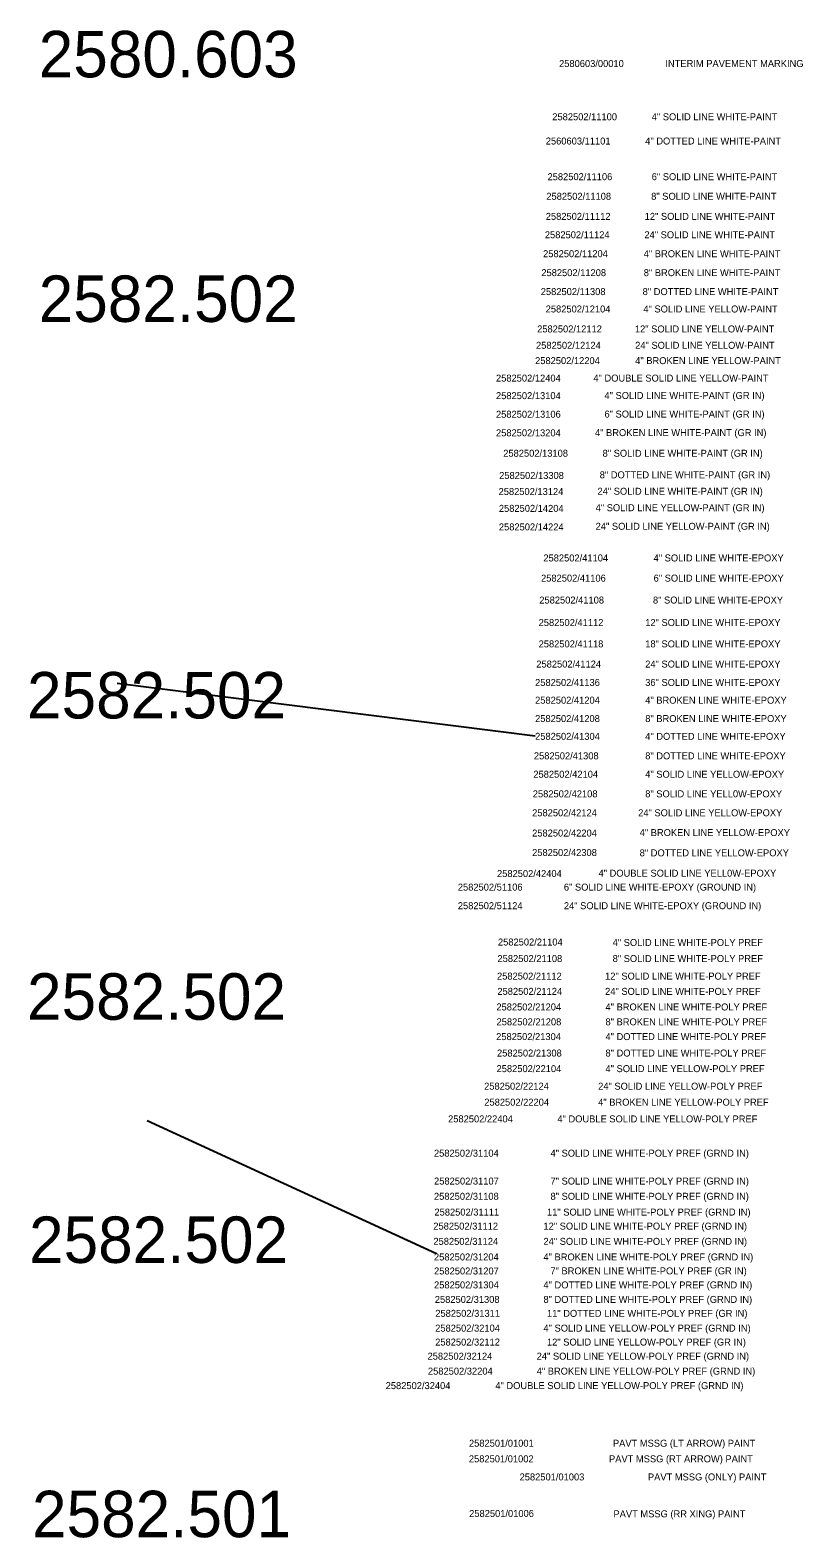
# Model space of a CAD drawing. Extents: x 2147712 to 2176316, y 2125036 to 2131746.
# Drawn here: x 2155869 to 2156701, y 2127854 to 2129477 of the extents above; entities that cross this region are included whole.
import ezdxf

# ---------------------------------------------------------------- set-up
doc = ezdxf.new("R2010")
doc.units = 0
doc.layers.add('DETAIL TXT', color=7, linetype='Continuous')
doc.layers.add('PVMT STRP', color=7, linetype='Continuous')

msp = doc.modelspace()

# ---------------------------------------------------------------- linework, layer by layer
at = {"layer": 'DETAIL TXT'}
for p, q in [((2156412.9, 2128716.8), (2155962.8, 2128773.5)), ((2156306.7, 2128159.6), (2155995.1, 2128302.9))]:
    msp.add_line(p, q, dxfattribs=at)

# ---------------------------------------------------------------- texts
for s, height, p in [('2580.603', 50, (2155878.4, 2129426.1)), ('2580603/00010', 7.5, (2156438.7, 2129437.2)), ('INTERIM PAVEMENT MARKING', 7.5, (2156553.2, 2129437.2)), ('2582502/11100', 7.5, (2156431.4, 2129379.9)), ('4" SOLID LINE WHITE-PAINT', 7.5, (2156538.5, 2129379.9)), ('2560603/11101', 7.5, (2156424.4, 2129353.8)), ('4" DOTTED LINE WHITE-PAINT', 7.5, (2156531.5, 2129353.8)), ('2582502/11106', 7.5, (2156426.3, 2129315.4)), ('6" SOLID LINE WHITE-PAINT', 7.5, (2156538.5, 2129315.4)), ('2582502/11108', 7.5, (2156425, 2129294.3)), ('8" SOLID LINE WHITE-PAINT', 7.5, (2156537.9, 2129294.3)), ('2582502/11112', 7.5, (2156424.4, 2129272.7)), ('12" SOLID LINE WHITE-PAINT', 7.5, (2156530.9, 2129272.7)), ('2582502/11124', 7.5, (2156423.4, 2129252.9)), ('24" SOLID LINE WHITE-PAINT', 7.5, (2156530.6, 2129252.9)), ('2582502/11204', 7.5, (2156421.5, 2129232.5)), ('4" BROKEN LINE WHITE-PAINT', 7.5, (2156529.9, 2129232.5)), ('2582.502', 50, (2155878.4, 2129162.8)), ('2582502/11208', 7.5, (2156419.6, 2129212.1)), ('8" BROKEN LINE WHITE-PAINT', 7.5, (2156529.9, 2129212.1)), ('2582502/11308', 7.5, (2156419, 2129191.7)), ('8" DOTTED LINE WHITE-PAINT', 7.5, (2156528.7, 2129191.7)), ('2582502/12104', 7.5, (2156424.3, 2129173)), ('4" SOLID LINE YELLOW-PAINT', 7.5, (2156529.5, 2129173)), ('2582502/12112', 7.5, (2156415.1, 2129151.5)), ('12" SOLID LINE YELLOW-PAINT', 7.5, (2156520.4, 2129151.5)), ('2582502/12124', 7.5, (2156413.9, 2129133.9)), ('24" SOLID LINE YELLOW-PAINT', 7.5, (2156520.7, 2129133.9)), ('2582502/12204', 7.5, (2156412.9, 2129117.4)), ('4" BROKEN LINE YELLOW-PAINT', 7.5, (2156520.7, 2129117.4)), ('2582502/12404', 7.5, (2156370.8, 2129098.6)), ('4" DOUBLE SOLID LINE YELLOW-PAINT', 7.5, (2156475.7, 2129098.6)), ('2582502/13104', 7.5, (2156370.8, 2129079.7)), ('4" SOLID LINE WHITE-PAINT (GR IN)', 7.5, (2156487.6, 2129079.9)), ('2582502/13106', 7.5, (2156370.8, 2129059.7)), ('6" SOLID LINE WHITE-PAINT (GR IN)', 7.5, (2156487.6, 2129059.9)), ('2582502/13204', 7.5, (2156370.8, 2129039.7)), ('4" BROKEN LINE WHITE-PAINT (GR IN)', 7.5, (2156477.4, 2129039.9)), ('2582502/13108', 7.5, (2156378.6, 2129017.7)), ('8" SOLID LINE WHITE-PAINT (GR IN)', 7.5, (2156485.6, 2129017.7)), ('2582502/13308', 7.5, (2156374.2, 2128993.8)), ('8" DOTTED LINE WHITE-PAINT (GR IN)', 7.5, (2156482.5, 2128994.5)), ('2582502/13124', 7.5, (2156373.6, 2128976.5)), ('24" SOLID LINE WHITE-PAINT (GR IN)', 7.5, (2156480.1, 2128976.8)), ('2582502/14204', 7.5, (2156373.9, 2128958.4)), ('4" SOLID LINE YELLOW-PAINT (GR IN)', 7.5, (2156478.1, 2128959.1)), ('2582502/14224', 7.5, (2156373.9, 2128938.4)), ('24" SOLID LINE YELLOW-PAINT (GR IN)', 7.5, (2156478.1, 2128939.1)), ('2582502/41104', 7.5, (2156421.8, 2128905)), ('4" SOLID LINE WHITE-EPOXY', 7.5, (2156540.5, 2128905)), ('2582502/41106', 7.5, (2156419.3, 2128883.3)), ('6" SOLID LINE WHITE-EPOXY', 7.5, (2156540.5, 2128883.3)), ('2582502/41108', 7.5, (2156417.4, 2128859.7)), ('8" SOLID LINE WHITE-EPOXY', 7.5, (2156539.8, 2128859.7)), ('2582502/41112', 7.5, (2156416.7, 2128835.5)), ('12" SOLID LINE WHITE-EPOXY', 7.5, (2156531.5, 2128835.5)), ('2582502/41118', 7.5, (2156416.7, 2128812.5)), ('18" SOLID LINE WHITE-EPOXY', 7.5, (2156531.5, 2128812.5)), ('2582502/41124', 7.5, (2156414.2, 2128790.8)), ('24" SOLID LINE WHITE-EPOXY', 7.5, (2156531.5, 2128790.8)), ('2582.502', 50, (2155865.8, 2128736)), ('2582502/41136', 7.5, (2156412.9, 2128771)), ('36" SOLID LINE WHITE-EPOXY', 7.5, (2156531.5, 2128771)), ('2582502/41204', 7.5, (2156412.9, 2128751.9)), ('4" BROKEN LINE WHITE-EPOXY', 7.5, (2156531.5, 2128751.9)), ('2582502/41208', 7.5, (2156412.9, 2128732.1)), ('8" BROKEN LINE WHITE-EPOXY', 7.5, (2156531.5, 2128732.1)), ('4" DOTTED LINE WHITE-EPOXY', 7.5, (2156531.5, 2128713)), ('2582502/41308', 7.5, (2156411.6, 2128692)), ('8" DOTTED LINE WHITE-EPOXY', 7.5, (2156531.5, 2128692)), ('2582502/42104', 7.5, (2156411, 2128672.2)), ('4" SOLID LINE YELLOW-EPOXY', 7.5, (2156531.5, 2128672.2)), ('2582502/42108', 7.5, (2156410.4, 2128651.1)), ('8" SOLID LINE YELL0W-EPOXY', 7.5, (2156531.5, 2128651.1)), ('2582502/42124', 7.5, (2156409.7, 2128630.7)), ('24" SOLID LINE YELLOW-EPOXY', 7.5, (2156523.9, 2128630.7)), ('2582502/42204', 7.5, (2156409.7, 2128608.9)), ('4" BROKEN LINE YELLOW-EPOXY', 7.5, (2156525.5, 2128609.4)), ('2582502/42308', 7.5, (2156409.7, 2128587.9)), ('8" DOTTED LINE YELLOW-EPOXY', 7.5, (2156525.5, 2128587.6)), ('2582502/42404', 7.5, (2156371.9, 2128565.3)), ('4" DOUBLE SOLID LINE YELL0W-EPOXY', 7.5, (2156481.2, 2128565.7)), ('2582502/51106', 7.5, (2156329.7, 2128550.7)), ('6" SOLID LINE WHITE-EPOXY (GROUND IN)', 7.5, (2156443.9, 2128550.7)), ('2582502/51124', 7.5, (2156329.7, 2128530.7)), ('24" SOLID LINE WHITE-EPOXY (GROUND IN)', 7.5, (2156443.9, 2128530.7)), ('2582502/21104', 7.5, (2156372.9, 2128491.6)), ('4" SOLID LINE WHITE-POLY PREF', 7.5, (2156496.4, 2128491.1)), ('2582502/21108', 7.5, (2156372.4, 2128473.8)), ('8" SOLID LINE WHITE-POLY PREF', 7.5, (2156496.4, 2128473.8)), ('2582.502', 50, (2155865.8, 2128411.7)), ('2582502/21112', 7.5, (2156371.9, 2128454.9)), ('12" SOLID LINE WHITE-POLY PREF', 7.5, (2156488.3, 2128454.9)), ('2582502/21124', 7.5, (2156372.3, 2128438.5)), ('24" SOLID LINE WHITE-POLY PREF', 7.5, (2156488.3, 2128438.5)), ('2582502/21204', 7.5, (2156371.2, 2128421.7)), ('4" BROKEN LINE WHITE-POLY PREF', 7.5, (2156488.7, 2128421.7)), ('2582502/21208', 7.5, (2156371.4, 2128405.7)), ('8" BROKEN LINE WHITE-POLY PREF', 7.5, (2156488.7, 2128405.7)), ('2582502/21304', 7.5, (2156371, 2128389.8)), ('4" DOTTED LINE WHITE-POLY PREF', 7.5, (2156488.7, 2128389.8)), ('2582502/21308', 7.5, (2156371.9, 2128372.1)), ('8" DOTTED LINE WHITE-POLY PREF', 7.5, (2156488.7, 2128372.1)), ('2582502/22104', 7.5, (2156371.4, 2128355.3)), ('4" SOLID LINE YELLOW-POLY PREF', 7.5, (2156488.7, 2128355.3)), ('2582502/22124', 7.5, (2156358, 2128336.4)), ('24" SOLID LINE YELLOW-POLY PREF', 7.5, (2156480.8, 2128336.4)), ('2582502/22204', 7.5, (2156358.2, 2128319.2)), ('4" BROKEN LINE YELLOW-POLY PREF', 7.5, (2156480.8, 2128319.2)), ('2582502/22404', 7.5, (2156319.2, 2128301.2)), ('4" DOUBLE SOLID LINE YELLOW-POLY PREF', 7.5, (2156436.9, 2128301.2)), ('2582502/31104', 7.5, (2156304, 2128264.3)), ('4" SOLID LINE WHITE-POLY PREF (GRND IN)', 7.5, (2156429.5, 2128264.3)), ('2582502/31107', 7.5, (2156304.1, 2128234.3)), ('7" SOLID LINE WHITE-POLY PREF (GRND IN)', 7.5, (2156429.5, 2128234.3)), ('2582502/31108', 7.5, (2156304, 2128217.9)), ('8" SOLID LINE WHITE-POLY PREF (GRND IN)', 7.5, (2156429.5, 2128217.9)), ('2582502/31111', 7.5, (2156304.5, 2128200.9)), ('11" SOLID LINE WHITE-POLY PREF (GRND IN)', 7.5, (2156425.7, 2128200.9)), ('2582.502', 50, (2155868, 2128149.9)), ('2582502/31112', 7.5, (2156303.3, 2128185.8)), ('12" SOLID LINE WHITE-POLY PREF (GRND IN)', 7.5, (2156421.9, 2128185.8)), ('2582502/31124', 7.5, (2156303.4, 2128169.4)), ('24" SOLID LINE WHITE-POLY PREF (GRND IN)', 7.5, (2156421.9, 2128169.4)), ('2582502/31204', 7.5, (2156304, 2128152.6)), ('4" BROKEN LINE WHITE-POLY PREF (GRND IN)', 7.5, (2156421.9, 2128152.6)), ('7" BROKEN LINE WHITE-POLY PREF (GR IN)', 7.5, (2156429.4, 2128137.6)), ('2582502/31304', 7.5, (2156304.1, 2128122.5)), ('4" DOTTED LINE WHITE-POLY PREF (GRND IN)', 7.5, (2156421.9, 2128122.5)), ('2582502/31308', 7.5, (2156304.9, 2128106.9)), ('8" DOTTED LINE WHITE-POLY PREF (GRND IN)', 7.5, (2156421.9, 2128106.9)), ('2582502/31311', 7.5, (2156305.4, 2128091.9)), ('11" DOTTED LINE WHITE-POLY PREF (GR IN)', 7.5, (2156425.7, 2128091.9)), ('2582502/32104', 7.5, (2156305.3, 2128076)), ('4" SOLID LINE YELLOW-POLY PREF (GRND IN)', 7.5, (2156421.9, 2128076)), ('2582502/32112', 7.5, (2156305.3, 2128061)), ('12" SOLID LINE YELLOW-POLY PREF (GR IN)', 7.5, (2156425.7, 2128061)), ('2582502/32124', 7.5, (2156297.1, 2128045.8)), ('24" SOLID LINE YELLOW-POLY PREF (GRND IN)', 7.5, (2156414.6, 2128045.8)), ('2582502/32204', 7.5, (2156297.5, 2128029.7)), ('4" BROKEN LINE YELLOW-POLY PREF (GRND IN)', 7.5, (2156414.6, 2128029.7)), ('2582502/32404', 7.5, (2156252, 2128014.1)), ('4" DOUBLE SOLID LINE YELLOW-POLY PREF (GRND IN)', 7.5, (2156370.1, 2128014.1)), ('2582501/01001', 7.5, (2156341.7, 2127952.1)), ('PAVT MSSG (LT ARROW) PAINT', 7.5, (2156496.7, 2127952.1)), ('2582501/01002', 7.5, (2156341.6, 2127935.3)), ('PAVT MSSG (RT ARROW) PAINT', 7.5, (2156492.5, 2127935.3)), ('2582501/01003', 7.5, (2156396.2, 2127915.8)), ('PAVT MSSG (ONLY) PAINT', 7.5, (2156534.4, 2127915.8)), ('2582.501', 50, (2155871.2, 2127854.7)), ('2582501/01006', 7.5, (2156341.9, 2127876.5)), ('PAVT MSSG (RR XING) PAINT', 7.5, (2156497.3, 2127876.1))]:
    msp.add_text(s, height=height, dxfattribs=at).set_placement(p)
at = {"layer": 'PVMT STRP'}
for s, p in [('2582502/41304', (2156412.9, 2128713)), ('2582502/31207', (2156304.1, 2128137.5))]:
    msp.add_text(s, height=7.5, dxfattribs=at).set_placement(p)

doc.saveas('drawing.dxf')
